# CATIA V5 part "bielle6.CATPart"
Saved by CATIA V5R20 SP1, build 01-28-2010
Part number: Part1
Bounding box of the stored display mesh (mm): x 13 to 87, y -20 to 5, z 28.093 to 41.907
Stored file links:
  E:\EDELI\gcausse\Edeli_2012_686_gcausse\bielle6.CATPart
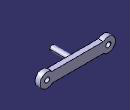
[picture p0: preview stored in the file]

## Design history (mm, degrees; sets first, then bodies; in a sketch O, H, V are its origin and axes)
Parameters
  long = 0.06
  diamtrou = 0.005
Body1 (main body)
  Sketch1 on zx-plane, origin (0, 0, 0), H (-1, 0, 0), V (0, 0, 1)
    line L1 (-24.899, 40) -> (-75.101, 40)
    line L2 (-24.899, 30) -> (-75.101, 30)
    arc A1 centre (-20, 35) radius 7 from (-24.899, 40) to (-24.899, 30) cw
    point P5 (-20, 35)
    point P6 (-15.101, 30)
    arc A2 centre (-80, 35) radius 7 from (-75.101, 40) to (-75.101, 30) ccw
    point P7 (-80, 35)
    circle A3 centre (-20, 35) radius 2.5
    distance P7 L1 = 5
    distance P5 L2 = 5
    distance L2 L1 = 10
    radius A1 = 7
    radius A2 = 7
    distance P5 P7 = 60 {= long}
    radius A3 = 2.5
    horizontal: L1 H, L2 H
    coincidence: A1 P6, P6 L2
  Pad1: profile Sketch1, direction (0, 1, 0), length 5
  Sketch2 on start face of Pad1, origin (81.911, 0, 35), H (1, 0, 0), V (0, 0, 1)
    point P1 (-1.911, 0)
    reference projected arc E1 centre (-1.911, 0) radius 7 from (-6.81, -5) to (-6.81, 5) ccw from edge [start face of Pad1 | face of Pad1 from Sketch1.A2]
    concentricity: P1 E1
  Hole1: placed by Sketch2, at (80, 0, 35) direction (0, 1, 0), diameter 5, depth 5
  DatumCurve1
  DatumCurve2
  Sketch3 on end face of Pad1, origin (0, 5, 0), H (-1, 0, 0), V (0, 0, 1)
    circle A1 centre (-50, 35) radius 2.5
    point P1 (-50, 35)
    reference projected line E1 (-24.899, 40) -> (-75.101, 40) from edge [face of Pad1 from Sketch1.L1 | end face of Pad1]
    reference projected line E2 (-75.101, 30) -> (-24.899, 30) from edge [face of Pad1 from Sketch1.L2 | end face of Pad1]
    reference projected point E3 (-20, 35) from edge of DatumCurve1
    reference projected point E4 (-80, 35) from edge of DatumCurve2
    radius A1 = 2.5
    equidistance: E1 E2 P1, E3 E4 P1
  Pad2: profile Sketch3, direction (0, 1, 0), length -25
